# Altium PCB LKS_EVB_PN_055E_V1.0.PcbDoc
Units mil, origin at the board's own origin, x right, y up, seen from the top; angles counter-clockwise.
Board outline 1880 x 1275 mil, 2 copper layers (Top Layer, Bottom Layer); 20 components, 24 nets, 82 pads, 53 vias.
Unrouted connection lines stored in the file: 3.
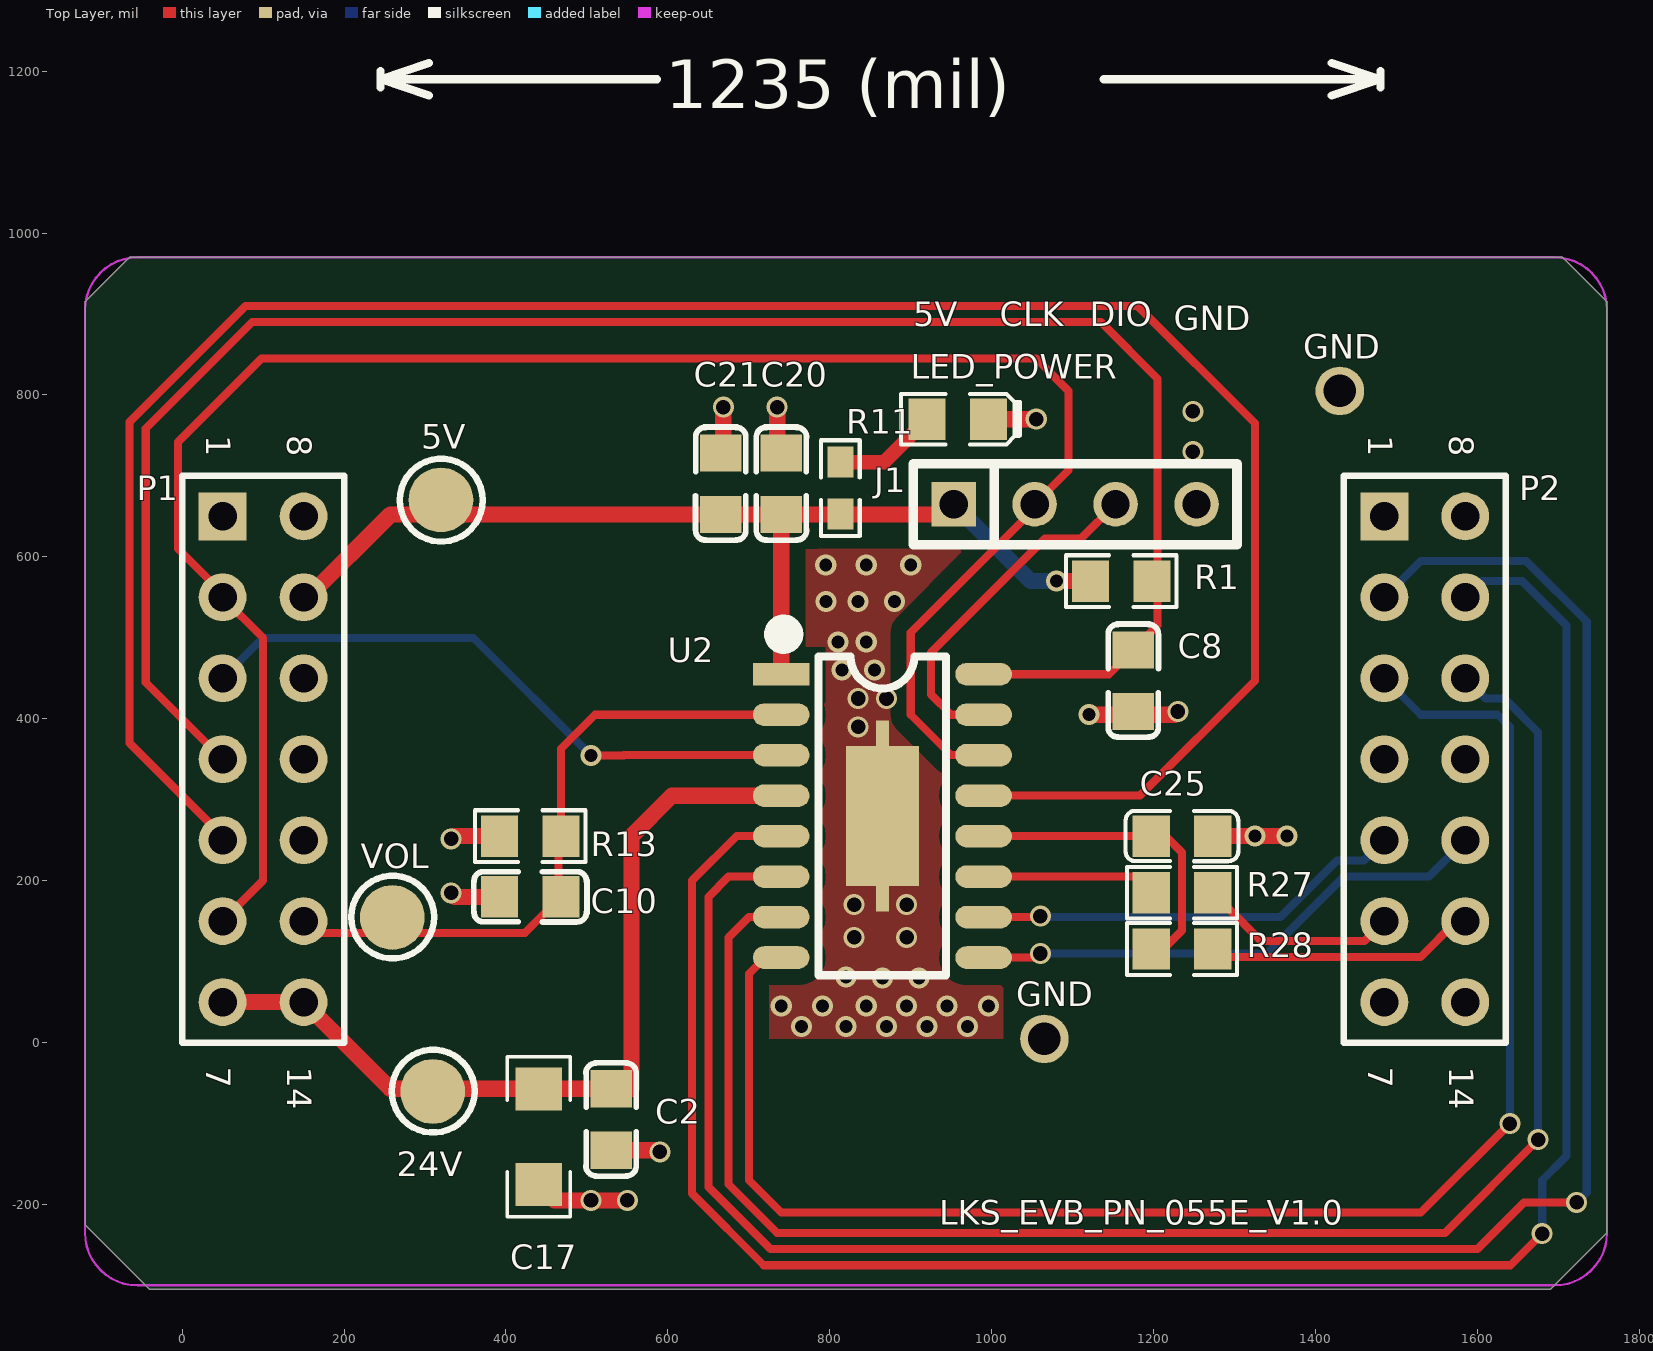
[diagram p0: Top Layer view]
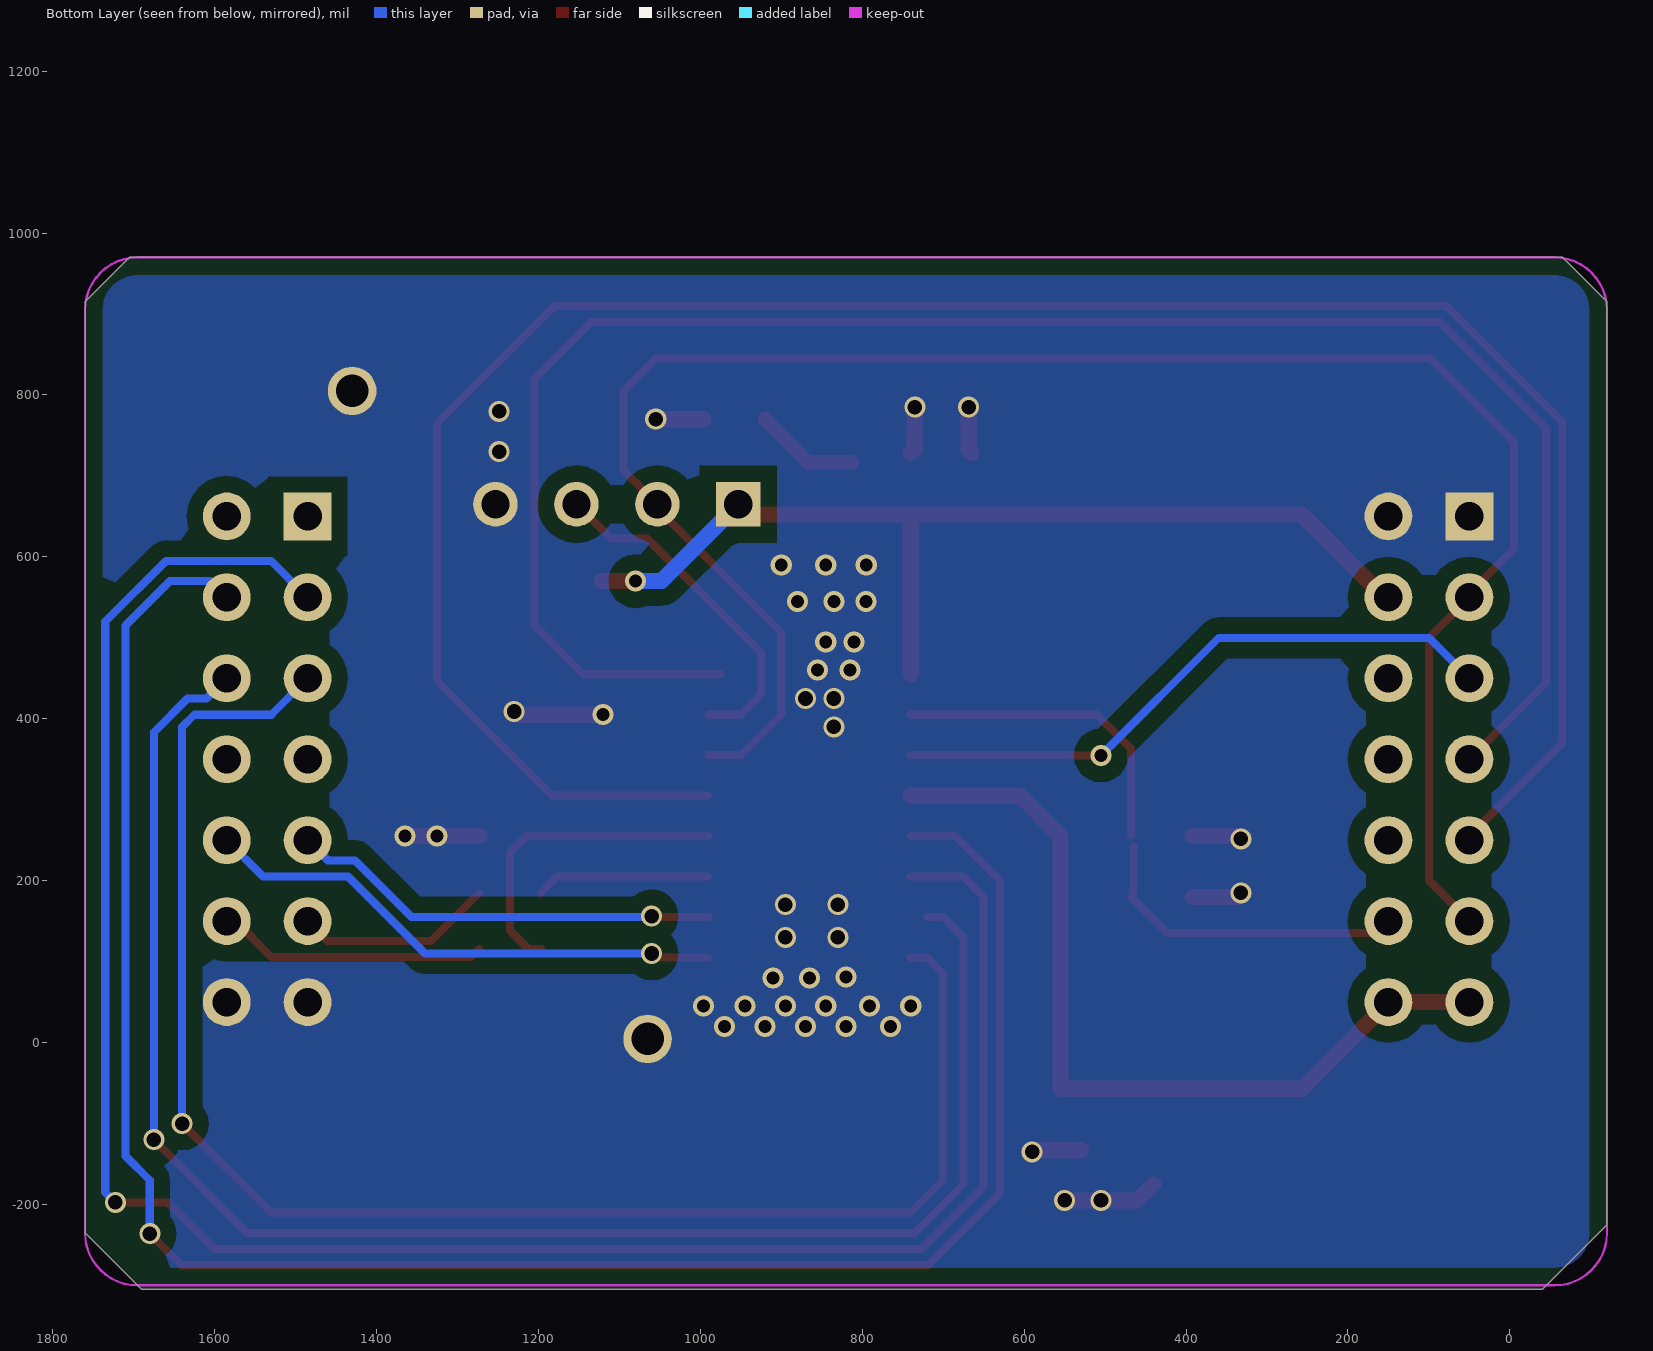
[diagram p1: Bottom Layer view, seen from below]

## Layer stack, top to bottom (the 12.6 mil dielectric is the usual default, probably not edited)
Top Layer: signal copper 1.4
Dielectric: dielectric 12.6, FR-4, Dk 4.8
Bottom Layer: signal copper 1.4

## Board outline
-120,-225 -40,-305 1690,-305 1760,-235 1760,915 1705,970 -65,970 -120,915

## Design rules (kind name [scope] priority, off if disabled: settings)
Clearance Clearance_1 [INPolygon] p1: gap=20
Clearance [All] p2: gap=10
ComponentClearance [All] p1: gap=0 collisioncheckmode=3 verticalgap=0 showdistances=FALSE
FabricationTestpoint [(IsPad And (OnTopLayer Or OnBottomLayer))] p1: side=3 testpointundercomponent=TRUE minsize=40 maxsize=100 preferedsize=60 minholesize=0 maxholesize=40 preferedholesize=32 testpointgrid=1 allowsidetop=TRUE allowsidebottom=TRUE usegrid=TRUE gridtolerance=0.01
PolygonConnect [All] p1: connectstyle=Direct reliefconductorwidth=20 reliefentries=4 polygonreliefangle="90 Angle"
RoutingVias [All] p1: holewidth=28 width=50 viastyle="Through Hole" minholewidth=28 minwidth=50 maxholewidth=28 maxwidth=50
SilkscreenOverComponentPads [IsPad] p1: minsilkscreentomaskgap=10
SolderMaskExpansion [All] p1: expansion=4
Width [All] p1: maxlimit=300 minlimit=1 preferedwidth=10
25 further rules are at their usual default settings.

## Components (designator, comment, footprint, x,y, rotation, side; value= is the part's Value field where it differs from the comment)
5V "TestP" TP-80 320,670 r0 top
24V "TestP" TP-80 310,-60 r90 top
C2 "100nF" 0805C 530,-95 r270 top
C8 "100nF" 0805C 1175,447 r270 top
C10 "100nF" 0805C 430,180 r180 top
C17 "10uF/50V" 1206 440,-175 r90 top
C20 "100nF" 0805C 740.04,690.32 r90 top
C21 "10uF/10V" 0805C 665.04,690.32 r90 top
C25 "100pF/50V" 0805C 1235,255 r180 top
J1 "SWD" SIP4-2.5 1103,665 r0 top
LED_POWER "" 0805D 958,770 r0 top
P1 "Header 7X2A" HDR2X7_CEN 50,650 r270 top locked
P2 "Header 7X2A" HDR2X7_CEN 1485,650 r270 top locked
R1 "20K" 0805R 1160,570 r0 top
R11 "3.3K" 0603R 813,685 r270 top
R13 "3.3K" 0805R 430,255 r180 top
R27 "1K" 0805R 1235,185 r0 top
R28 "1K" 0805R 1235,115.59 r0 top
U2 "LKS055E" ESOP16(513) 865,280 r0 top
VOL "TestP" TP-80 260,155 r90 top

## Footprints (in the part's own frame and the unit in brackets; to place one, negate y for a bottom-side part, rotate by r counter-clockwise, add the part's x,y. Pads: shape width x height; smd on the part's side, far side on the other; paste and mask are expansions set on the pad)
0603R [mil]
  rect 38x32 smd: 1(-32,0) 2(32,0)
  silkscreen extent -59,-24 59,24, body extent -31,-16 32,16, height 18
0805C [mil]
  rect 46x51.18 smd: 1(-38,0) 2(38,0)
  silkscreen extent -70,-31 70,31
0805D [mil]
  rect 46x51.18 smd: 1(-38,0) 2(38,0)
  silkscreen extent -70,-31 77,31, body extent -39,-25 39,25, height 22
0805R [mil]
  rect 46x51.18 smd: 1(-38,0) 2(38,0)
  silkscreen extent -68,-32 68,32
1206 [mm]
  rect 1.35x1.45 smd: 1(-0.01,-0.01) 2(2.99,-0.01)
  silkscreen extent -1.02,-1 4,0.98
ESOP16(513) [mil]
  rect 90.55x173.23 smd: 0(0,0)
  rect 15.75x31.5 smd: 0(0,102.36) 0(0,-102.36)
  rect 70x28 smd: 1(-125,175)
  oval 70x28 smd: 2(-125,125) 3(-125,75) 4(-125,25) 5(-125,-25) 6(-125,-75) 7(-125,-125) 8(-125,-175) 9(125,-175) 10(125,-125) 11(125,-75) 12(125,-25) 13(125,25) 14(125,75) 15(125,125) 16(125,175)
  silkscreen extent -134,-197 79,236
HDR2X7_CEN [mm] "Connector; Header; 7x2 Position"
  rect 1.5x1.5 hole 0.9: 1(0,0)
  round 1.5 hole 0.9: 2(2.54,0) 3(5.08,0) 4(7.62,0) 5(10.16,0) 6(12.7,0) 7(15.24,0) 8(0,2.54) 9(2.54,2.54) 10(5.08,2.54) 11(7.62,2.54) 12(10.16,2.54) 13(12.7,2.54) 14(15.24,2.54)
  silkscreen extent -1.27,-1.27 16.51,3.81
SIP4-2.5 [mil]
  rect 55x55 hole 35: 1(-150,0)
  round 55 hole 35: 2(-50,0) 3(50,0) 4(150,0)
  silkscreen extent -200,-50 200,50
TP-80 [mil]
  round 80 smd: 1(-0.39,0.39)
  silkscreen extent -51,-51 51,51

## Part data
C2 C10 C17: library part CAP, "Capacitor"
C8 C20 C21 C25: library part C, "Capacitor"
J1: library part "Header 4", "Header, 4-Pin"
LED_POWER: library part LED2, "Typical RED, GREEN, YELLOW, AMBER GaAs LED"
P1 P2: "Header, 7-Pin, Dual row"
R1 R27 R28: library part RES2-1
R11 R13: library part Res2, "Resistor"

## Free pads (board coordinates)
  round 60 hole 40: 6(1065,4.61) 7(1430,805)

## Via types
v1: diameter 26, hole 16, Top Layer to Bottom Layer, 29 vias
v2: diameter 25.98, hole 17.99, Top Layer to Bottom Layer, 24 vias

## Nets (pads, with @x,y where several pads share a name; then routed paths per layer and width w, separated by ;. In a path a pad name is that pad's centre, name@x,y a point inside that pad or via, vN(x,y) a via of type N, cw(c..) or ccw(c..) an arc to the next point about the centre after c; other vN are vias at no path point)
5V: 5V.1 C20.1 C21.1 J1.1 P1.9 R1.1 R11.2 U2.1 | length 1251
  Top Layer w20: P1.9@155,550 257.32,652.32 C21.1 C20.1 940.32,652.32 J1.1 ; U2.1 C20.1@740,652 ; v1(1080,570) R1.1
  Bottom Layer w20: J1.1 1048,570 v1(1080,570)
24V_MCU: 24V.1 C2.1 C17.2 P1.7 P1.14 U2.4 | length 1067
  Top Layer w20: P1.7 P1.14 257,-57 555,-57 555,255 605,305 U2.4
FG: J1.2 P1.2 P1.6 U2.14 | length 2402.2
  Top Layer w10: P1.6 100,200 100,500 P1.2 ; P1.2@55,550 -5,610 -5,741.86 98.14,845 1055,845 1095,805 1095,707 J1.2 ; U2.14 950,355 900,405 900,506.72 1049.57,656.28 J1.2@1053,656.28
G: P2.1 P2.4 P2.13 R28.2 | length 334.6
  Top Layer w10: R28.2 1283.12,105.47 1426.24,105.47 1529.53,105.47 1574.06,150 P2.13
GND: C2.2 C8.2 C10.2 C17.1 C20.2 C21.2 C25.1 J1.4 LED_POWER.2 P1.1 P1.8 P2.6 P2.7 P2.14 pad.6 pad.7 R13.2 R27.2 U2.0 | length 928.1
  Top Layer w10: R27.2 1301.82,156.18 1302.21,156.18 1311,147.39 1311,147 1332.47,125.53 1460.53,125.53 P2.6
  Top Layer w20: v2(332.17,185) 337.17,180 C10.2 ; v2(332.24,251.63) 335.61,255 R13.2 ; C17.1 460,-195 v2(505,-195) v2(550,-195) ; C2.2 588,-133 v2(590,-135) ; C21.2 668.41,731.68 v2(668.41,785) ; v2(735,785) 735,733.35 C20.2 ; LED_POWER.2 v2(1055,770) ; v1(1120,405) 1226,405 v2(1230,409) ; C25.1 v1(1365,255)
  other v1: 765,20 820,20 870,20 920,20 970,20 740.04,45 790.7,45 845,45 895,45 944.75,45 996,45 865,80 910,80 820,80.75 1325,255 815,460 855,460 810,495 845,495 795.29,545 835,545 880,545 795,590 845,590 900,590
  other v2: 830,130 895,130 830,170.3 895,170.3 835,390 835,425 870,425 1248.44,730 1248.44,779.74
HU&PU: P1.10
HV&PV: P1.11
HW&PW: P1.12
NetLED_POWER_1: LED_POWER.1 R11.1 | length 129
  Top Layer w17.87: R11.1 867,717 LED_POWER.1
NRST: C8.1 P1.4 R1.2 U2.16 | length 2341.1
  Top Layer w10: P1.4 -45,445 -45,758.43 86.57,890 1135,890 1205,820 1205,515 1145,455 U2.16@975,455
OPA1_IN: R27.1 U2.11 | length 215.3
  Top Layer w10: U2.11 1177,205 R27.1
OPA1_IP: C25.2 R28.1 U2.12 | length 397.3
  Top Layer w10: U2.12 1215,255 1235,235 1235,138.45 1212.14,115.59 R28.1
SPIN: P1.3 U2.3 | length 770.5
  Top Layer w10: v1(505,354.61) 545.39,354.61 ; 545.79,355 U2.3
  Bottom Layer w10: P1.3 100,500 359.61,500 v1(505,354.61)
SWDIO: J1.3 U2.15 | length 431
  Top Layer w10: U2.15 950,405 925,430 925,481.72 1065.78,622.5 1110.5,622.5 J1.3
TXD: P1.5 U2.13 | length 2780.6
  Top Layer w10: P1.5@50,255 -65,370 -65,766.72 78.28,910 1180,910 1325,765 1325,447 1183,305 U2.13
UH: P2.9 U2.5 | length 2540.7
  Top Layer w10: U2.5 685,255 630,200 630,-186.57 718.43,-275 1640.9,-275 v2(1680,-235.9)
  Bottom Layer w10: P2.9 1605,570 1655,570 1710,515 1710,-140 1680,-170 v2@1680,-235
UL: P2.2 U2.6 | length 2609.1
  Top Layer w10: U2.6 675,205 650,180 650,-178.28 726.72,-255 1600,-255 1657.5,-197.5 v2(1722.5,-197.5)
  Bottom Layer w10: P2.2 1530,595 1660,595 1735,520 1735,-185 v2(1722.5,-197.5)
UX: P2.8
VH: P2.10 U2.7 | length 2053.8
  Top Layer w10: U2.7@720,155 700,155 675,130 675,-175 735,-235 1560,-235 v2(1675,-120)
  Bottom Layer w10: P2.10 1610,425 1633.28,425 1675,383.28 v2(1675,-120)
VL: P2.3 U2.8 | length 1975.3
  Top Layer w10: U2.8 720,105 700,85 700,-170 740,-210 1530,-210 v2(1640,-100)
  Bottom Layer w10: P2.3 1530,405 1625,405 1640,390 v2(1640,-100)
VOL: C10.1 P1.13 R13.1 U2.2 VOL.1 | length 798.8
  Top Layer w10: P1.13@150,155 169.41,135.59 423.59,135.59 C10.1 ; C10.1@465,185 R13.1@465,242 ; R13.1 468,363 510,405 U2.2
VX: P2.11
WH: P2.12 U2.9 | length 655.1
  Top Layer w10: U2.9 1055,105 v2(1060,110)
  Bottom Layer w10: v2(1060,110) 1340,110 1435,205 1540,205 P2.12
WL: P2.5 U2.10 | length 533.2
  Top Layer w10: U2.10 v2@1058.82,155
  Bottom Layer w10: v2@1060,155 1356.72,155 1426.72,225 1460,225 P2.5
  other v2: 1060,156.18

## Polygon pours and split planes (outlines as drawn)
GND on Bottom Layer "Bottom Layer-No Net" (solid, remove dead copper, pour order 3): -125,970 -125,-300 1750,-300 1755,-295 1755,970
GND on Top Layer "Bottom Layer-No Net" (solid, remove dead copper, pour order 4): 710,610 710,4.61 1014.12,4.61 1014.12,440.17 1014.12,605.63 1020,610

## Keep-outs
Keep-Out Layer:
  lines w2.99: -120,-235 ccw(c-55,-235) -55,-300 ; -120,905 cw(c-55,905) -55,970 ; 1695,-300 ccw(c1695,-235) 1760,-235 ; 1695,970 cw(c1695,905) 1760,905
  lines w3: -120,-235 -120,905 ; -55,-300 1695,-300 ; -55,970 1695,970 ; 1760,-235 1760,905

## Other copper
Top Layer:
  pour cut-out: 1240,225 1410,225 1585,230 1585,215 1583.26,125.53 1555.86,125.53 1545,114.68 1542.96,116.72 1321.39,116.72 1240,115.59
Bottom Layer:
  pour cut-out: 1395,193.28 1566.72,193.28 1585,175 1585,100.05 1362.77,100.05 1352.81,110

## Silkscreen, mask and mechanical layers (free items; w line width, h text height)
Top Overlay:
  lines w10: 245,1180 245,1200 ; 305,1170 245,1190 ; 305,1210 245,1190 ; 586.58,1190 245,1190 ; 1138.42,1190 1480,1190 ; 1420,1170 1480,1190 ; 1420,1210 1480,1190 ; 1480,1180 1480,1200
  text "1235 (mil)" at 596.58,1154.01 h60
  text "5V" at 903,885 h30
  text "CLK" at 1010,885 h30
  text "DIO" at 1121.06,885 h30
  text "GND" at 1225,880 h30
  text "GND" at 1385,845 h30
  text "GND" at 1030,45 h30
  text "LKS_EVB_PN_055E_V1.0" at 935,-225 h30
  text "20210311" at 940,-425 h30
Mechanical 1:
  lines w10: -239.76,899.92 -220,960 ; -235.24,-245.08 -215,-305 ; -230,959.96 -210,960.04 ; -225,-305.04 -205,-304.96 ; -218.91,683.39 -220,960 ; -216.09,-28.39 -215,-305 ; -199.76,900.08 -220,960 ; -195.24,-244.92 -215,-305 ; -105.08,1024.84 -105.03,1044.84 ; -45.11,1014.68 -105.05,1034.84 ; -45,1054.68 -105.05,1034.84 ; 444.07,1033.38 -105.05,1034.84 ; 1225.82,1031.3 1774.95,1029.84 ; 1714.89,1010 1774.95,1029.84 ; 1715,1050 1774.95,1029.84 ; 1774.92,1019.84 1774.97,1039.84
  text "1880.007 (mil)" at 453.97,997.36 h60 r359.85
  text "1265.01 (mil)" at -254.86,673.24 h60 r270.23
